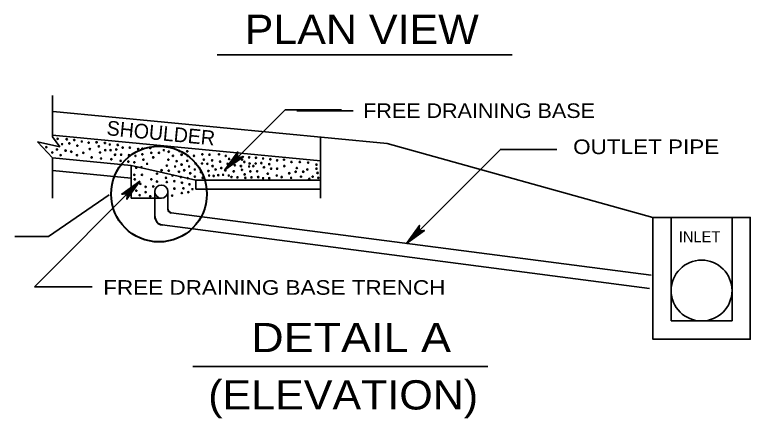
# Model space of a CAD drawing. Extents: x -48732 to -48696.6, y -117659.8 to -117637.8.
# Drawn here: x -48725.29 to -48719.25, y -117648.12 to -117644.8 of the extents above; entities that cross this region are included whole.
import ezdxf

# ---------------------------------------------------------------- set-up
doc = ezdxf.new("R2010")
doc.units = 0
doc.header["$LTSCALE"] = 0.048
doc.layers.add('1', color=7, linetype='Continuous', lineweight=25)
doc.layers.add('3', color=7, linetype='Continuous', lineweight=35)

msp = doc.modelspace()

# ---------------------------------------------------------------- linework, layer by layer
at = {"layer": '1', "lineweight": 40}
msp.add_circle((-48724.10882, -117646.27628), 0.39328, dxfattribs=at)
for centre, radius, end in [((-48724.00558, -117646.39991), 0.03, 262.57441), ((-48724.07358, -117646.45961), 0.07, 262.57442), ((-48724.07358, -117646.45961), 0.07, 262.57442)]:
    msp.add_arc(centre, radius, 180, end, dxfattribs=at)
at = {"layer": '3'}
for p, q in [((-48723.6305, -117645.13408), (-48721.20992, -117645.13408)), ((-48724.98458, -117645.46833), (-48724.98458, -117645.80533)), ((-48724.97758, -117645.59733), (-48722.23658, -117645.86133)), ((-48723.5735, -117646.08625), (-48723.0735, -117645.58625)), ((-48723.0735, -117645.58625), (-48722.6105, -117645.58625)), ((-48722.97633, -117645.5935), (-48722.51333, -117645.5935)), ((-48724.98458, -117645.79233), (-48722.78258, -117646.00433)), ((-48725.10558, -117645.84733), (-48724.98458, -117645.97933)), ((-48725.10558, -117645.84733), (-48724.92258, -117645.88733)), ((-48724.98458, -117645.80533), (-48724.92258, -117645.88733)), ((-48722.78258, -117645.80833), (-48722.78258, -117646.31033)), ((-48720.05358, -117646.46833), (-48722.23658, -117645.86133)), ((-48724.98458, -117645.97933), (-48724.98458, -117646.31033)), ((-48724.98458, -117646.08333), (-48724.33858, -117646.14533)), ((-48724.33858, -117646.04133), (-48723.80758, -117646.16333)), ((-48725.13233, -117647.03708), (-48724.26633, -117646.17108)), ((-48723.80758, -117646.16333), (-48722.78258, -117646.16333)), ((-48723.80758, -117646.23533), (-48723.80758, -117646.16333)), ((-48724.14358, -117646.25633), (-48724.14358, -117646.45958)), ((-48724.03558, -117646.25633), (-48724.03558, -117646.39992)), ((-48723.80758, -117646.23533), (-48722.78258, -117646.23533)), ((-48725.01625, -117646.62567), (-48724.51717, -117646.28358)), ((-48724.33858, -117646.31033), (-48724.08958, -117646.31033)), ((-48724.0095, -117646.42967), (-48720.0675, -117646.94342)), ((-48719.90358, -117647.31833), (-48719.90358, -117646.46833)), ((-48719.40358, -117646.46833), (-48719.40358, -117647.31833)), ((-48724.08267, -117646.529), (-48720.0815, -117647.0505)), ((-48725.29367, -117646.62567), (-48725.01625, -117646.62567)), ((-48725.13233, -117647.03708), (-48724.65858, -117647.03708)), ((-48719.40358, -117647.31833), (-48719.90358, -117647.31833)), ((-48723.83025, -117647.69208), (-48721.40967, -117647.69208))]:
    msp.add_line(p, q, dxfattribs=at)
for points in [[(-48722.07683, -117646.6815), (-48721.305, -117645.90967), (-48720.842, -117645.90967)], [(-48723.462, -117645.93042), (-48723.568, -117646.07842), (-48723.42, -117645.97242), (-48723.425, -117645.97242), (-48723.555, -117646.06542), (-48723.462, -117645.93542), (-48723.463, -117645.94142), (-48723.542, -117646.05242), (-48723.431, -117645.97342), (-48723.437, -117645.97442), (-48723.529, -117646.03942), (-48723.464, -117645.94742), (-48723.464, -117645.95342), (-48723.516, -117646.02642), (-48723.443, -117645.97442), (-48723.449, -117645.97542), (-48723.504, -117646.01442), (-48723.465, -117645.95942), (-48723.465, -117645.96542), (-48723.491, -117646.00142), (-48723.455, -117645.97542), (-48723.461, -117645.97642), (-48723.478, -117645.98842), (-48723.466, -117645.97142), (-48723.462, -117645.93042), (-48723.466, -117645.97642), (-48723.42, -117645.97242)], [(-48724.98458, -117645.97933), (-48724.33858, -117646.04133), (-48724.33858, -117646.31033)], [(-48724.37233, -117646.31908), (-48724.26633, -117646.17108), (-48724.41433, -117646.27708), (-48724.40933, -117646.27708), (-48724.27933, -117646.18408), (-48724.37233, -117646.31408), (-48724.37133, -117646.30808), (-48724.29233, -117646.19708), (-48724.40333, -117646.27608), (-48724.39733, -117646.27508), (-48724.30533, -117646.21008), (-48724.37033, -117646.30208), (-48724.37033, -117646.29608), (-48724.31833, -117646.22308), (-48724.39133, -117646.27508), (-48724.38533, -117646.27408), (-48724.33033, -117646.23508), (-48724.36933, -117646.29008), (-48724.36933, -117646.28408), (-48724.34333, -117646.24808), (-48724.37933, -117646.27408), (-48724.37333, -117646.27308), (-48724.35633, -117646.26108), (-48724.36833, -117646.27808), (-48724.37233, -117646.31908), (-48724.36833, -117646.27308), (-48724.41433, -117646.27708)], [(-48721.97083, -117646.5335), (-48722.07683, -117646.6815), (-48721.92883, -117646.5755), (-48721.93383, -117646.5755), (-48722.06383, -117646.6685), (-48721.97083, -117646.5385), (-48721.97183, -117646.5445), (-48722.05083, -117646.6555), (-48721.93983, -117646.5765), (-48721.94583, -117646.5775), (-48722.03783, -117646.6425), (-48721.97283, -117646.5505), (-48721.97283, -117646.5565), (-48722.02483, -117646.6295), (-48721.95183, -117646.5775), (-48721.95783, -117646.5785), (-48722.01283, -117646.6175), (-48721.97383, -117646.5625), (-48721.97383, -117646.5685), (-48721.99983, -117646.6045), (-48721.96383, -117646.5785), (-48721.96983, -117646.5795), (-48721.98683, -117646.5915), (-48721.97483, -117646.5745), (-48721.97083, -117646.5335), (-48721.97483, -117646.5795), (-48721.92883, -117646.5755)]]:
    msp.add_lwpolyline(points, dxfattribs=at)
msp.add_lwpolyline([(-48720.05358, -117646.46833), (-48719.25358, -117646.46833), (-48719.25358, -117647.46833), (-48720.05358, -117647.46833)], close=True, dxfattribs=at)
for centre, radius in [((-48724.94092, -117645.82333), 0.00515), ((-48724.8665, -117645.82642), 0.00515), ((-48724.80442, -117645.83267), 0.00515), ((-48724.74242, -117645.84508), 0.00515), ((-48724.68658, -117645.85442), 0.00515), ((-48724.62142, -117645.85125), 0.00515), ((-48724.55317, -117645.8575), 0.00515), ((-48725.034, -117645.89158), 0.00515), ((-48724.94717, -117645.91025), 0.00515), ((-48724.90375, -117645.86683), 0.00515), ((-48724.84542, -117645.86042), 0.00515), ((-48724.77958, -117645.87917), 0.00515), ((-48724.67725, -117645.90717), 0.00515), ((-48724.60275, -117645.88542), 0.00515), ((-48724.55008, -117645.91642), 0.00515), ((-48724.51283, -117645.86992), 0.00515), ((-48724.50658, -117645.91642), 0.00515), ((-48724.46008, -117645.91025), 0.00515), ((-48724.44767, -117645.873), 0.00515), ((-48724.40733, -117645.89475), 0.00515), ((-48724.34842, -117645.89475), 0.00515), ((-48724.28017, -117645.90717), 0.00515), ((-48724.246, -117645.904), 0.00515), ((-48724.18092, -117645.89783), 0.00515), ((-48724.06917, -117645.91642), 0.00515), ((-48724.98433, -117645.93508), 0.00515), ((-48724.91608, -117645.95683), 0.00515), ((-48724.87575, -117645.91958), 0.00515), ((-48724.82925, -117645.92883), 0.00515), ((-48724.78275, -117645.95683), 0.00515), ((-48724.73, -117645.93817), 0.00515), ((-48724.66175, -117645.97542), 0.00515), ((-48724.5935, -117645.93508), 0.00515), ((-48724.46942, -117645.95367), 0.00515), ((-48724.41975, -117645.95367), 0.00515), ((-48724.35458, -117645.95683), 0.00515), ((-48724.30183, -117645.963), 0.00515), ((-48724.246, -117645.95058), 0.00515), ((-48724.17158, -117645.93817), 0.00515), ((-48724.15608, -117645.97542), 0.00515), ((-48724.1095, -117645.93817), 0.00515), ((-48724.02883, -117645.92883), 0.00515), ((-48723.99475, -117645.963), 0.00515), ((-48723.942, -117645.92267), 0.00515), ((-48723.92342, -117645.95367), 0.00515), ((-48723.87683, -117645.92575), 0.00515), ((-48723.87375, -117645.963), 0.00515), ((-48723.821, -117645.963), 0.00515), ((-48723.75275, -117645.95058), 0.00515), ((-48723.69383, -117645.95367), 0.00515), ((-48723.61625, -117645.95058), 0.00515), ((-48723.56042, -117645.963), 0.00515), ((-48723.47667, -117645.95992), 0.00515), ((-48723.42083, -117645.97233), 0.00515), ((-48723.36808, -117645.97542), 0.00515), ((-48723.31225, -117645.9785), 0.00515), ((-48724.58417, -117645.98475), 0.00515), ((-48724.50042, -117645.99092), 0.00515), ((-48724.42283, -117646.00333), 0.00515), ((-48724.36083, -117646.00958), 0.00515), ((-48724.31117, -117646.01575), 0.00515), ((-48724.23675, -117645.99408), 0.00515), ((-48724.20567, -117646.02817), 0.00515), ((-48724.032, -117645.99408), 0.00515), ((-48723.96375, -117646.00642), 0.00515), ((-48723.92342, -117646.03442), 0.00515), ((-48723.87683, -117646.00333), 0.00515), ((-48723.80858, -117646.02508), 0.00515), ((-48723.75592, -117646.02508), 0.00515), ((-48723.74033, -117645.99408), 0.00515), ((-48723.71242, -117646.02817), 0.00515), ((-48723.67208, -117646.00025), 0.00515), ((-48723.607, -117646.00958), 0.00515), ((-48723.54492, -117646.02817), 0.00515), ((-48723.5325, -117645.98783), 0.00515), ((-48723.48292, -117645.99092), 0.00515), ((-48723.427, -117645.99408), 0.00515), ((-48723.40842, -117646.01267), 0.00515), ((-48723.365, -117646.02508), 0.00515), ((-48723.31533, -117646.02508), 0.00515), ((-48723.26883, -117646.022), 0.00515), ((-48723.25333, -117645.98475), 0.00515), ((-48723.20367, -117646.03125), 0.00515), ((-48723.19433, -117645.99092), 0.00515), ((-48723.1385, -117646.00025), 0.00515), ((-48723.08267, -117645.99408), 0.00515), ((-48723.02067, -117646.01267), 0.00515), ((-48722.95242, -117646.01267), 0.00515), ((-48722.88417, -117646.01883), 0.00515), ((-48722.81592, -117646.03442), 0.00515), ((-48724.29567, -117646.05925), 0.00515), ((-48724.25225, -117646.05608), 0.00515), ((-48724.08783, -117646.08092), 0.00515), ((-48724.04442, -117646.04367), 0.00515), ((-48724.02883, -117646.08408), 0.00515), ((-48723.97617, -117646.04992), 0.00515), ((-48723.94508, -117646.09333), 0.00515), ((-48723.90167, -117646.08092), 0.00515), ((-48723.86133, -117646.04992), 0.00515), ((-48723.81483, -117646.07475), 0.00515), ((-48723.76517, -117646.0965), 0.00515), ((-48723.70317, -117646.08717), 0.00515), ((-48723.669, -117646.04683), 0.00515), ((-48723.64417, -117646.07475), 0.00515), ((-48723.59767, -117646.06233), 0.00515), ((-48723.5635, -117646.08092), 0.00515), ((-48723.49525, -117646.09025), 0.00515), ((-48723.486, -117646.04058), 0.00515), ((-48723.43633, -117646.04683), 0.00515), ((-48723.427, -117646.07783), 0.00515), ((-48723.36808, -117646.04992), 0.00515), ((-48723.35875, -117646.09025), 0.00515), ((-48723.334, -117646.04683), 0.00515), ((-48723.30292, -117646.09025), 0.00515), ((-48723.24708, -117646.05608), 0.00515), ((-48723.18817, -117646.0685), 0.00515), ((-48723.1385, -117646.0685), 0.00515), ((-48723.07958, -117646.04683), 0.00515), ((-48722.9865, -117646.09333), 0.00515), ((-48722.97725, -117646.06233), 0.00515), ((-48722.9245, -117646.09333), 0.00515), ((-48722.89033, -117646.07475), 0.00515), ((-48722.81592, -117646.0685), 0.00515), ((-48724.31117, -117646.11817), 0.00515), ((-48724.30808, -117646.15542), 0.00515), ((-48724.24917, -117646.11817), 0.00515), ((-48724.17158, -117646.15542), 0.00515), ((-48724.12508, -117646.10892), 0.00515), ((-48724.05058, -117646.143), 0.00515), ((-48723.99783, -117646.12442), 0.00515), ((-48723.92958, -117646.13683), 0.00515), ((-48723.87375, -117646.14608), 0.00515), ((-48723.85208, -117646.10575), 0.00515), ((-48723.81483, -117646.13367), 0.00515), ((-48723.74967, -117646.143), 0.00515), ((-48723.69692, -117646.12442), 0.00515), ((-48723.65967, -117646.1275), 0.00515), ((-48723.6225, -117646.12133), 0.00515), ((-48723.58217, -117646.11817), 0.00515), ((-48723.53558, -117646.12442), 0.00515), ((-48723.51392, -117646.13683), 0.00515), ((-48723.46425, -117646.13992), 0.00515), ((-48723.40533, -117646.11508), 0.00515), ((-48723.39908, -117646.143), 0.00515), ((-48723.3495, -117646.13992), 0.00515), ((-48723.29367, -117646.13683), 0.00515), ((-48723.25333, -117646.14608), 0.00515), ((-48723.21608, -117646.10892), 0.00515), ((-48723.20367, -117646.14608), 0.00515), ((-48723.14167, -117646.12442), 0.00515), ((-48723.10133, -117646.13683), 0.00515), ((-48723.03925, -117646.10575), 0.00515), ((-48723.02375, -117646.143), 0.00515), ((-48722.94308, -117646.13367), 0.00515), ((-48722.87483, -117646.15233), 0.00515), ((-48722.84692, -117646.13367), 0.00515), ((-48722.80658, -117646.10267), 0.00515), ((-48722.80042, -117646.143), 0.00515), ((-48724.26158, -117646.19267), 0.00515), ((-48724.21808, -117646.2175), 0.00515), ((-48724.15608, -117646.21442), 0.00515), ((-48724.08958, -117646.25633), 0.054), ((-48724.12508, -117646.17408), 0.00515), ((-48724.04442, -117646.17717), 0.00515), ((-48723.98233, -117646.17092), 0.00515), ((-48723.92033, -117646.18333), 0.00515), ((-48723.85825, -117646.19575), 0.00515), ((-48724.29567, -117646.24858), 0.00515), ((-48724.21808, -117646.261), 0.00515), ((-48723.98231, -117646.23157), 0.00515), ((-48723.92173, -117646.26748), 0.00515), ((-48723.90823, -117646.22932), 0.00515), ((-48723.8679, -117646.26073), 0.00515), ((-48723.83423, -117646.23607), 0.00515), ((-48724.26775, -117646.28575), 0.00515), ((-48724.18092, -117646.29508), 0.00515), ((-48724.00031, -117646.2899), 0.00515), ((-48719.65358, -117647.06833), 0.25)]:
    msp.add_circle(centre, radius, dxfattribs=at)

# ---------------------------------------------------------------- texts
for s, height, width, p in [('PLAN VIEW', 0.24, 1.1, (-48723.40558, -117645.04417)), ('FREE DRAINING BASE', 0.12, 1.1, (-48722.43192, -117645.65192)), ('OUTLET PIPE', 0.12, 1.15, (-48720.70833, -117645.94833)), ('FREE DRAINING BASE TRENCH', 0.12, 1.15, (-48724.56658, -117647.10317)), ('DETAIL A', 0.24, 1.15, (-48723.35158, -117647.574)), ('(ELEVATION)', 0.24, 1.1, (-48723.70483, -117648.04475))]:
    msp.add_text(s, height=height, dxfattribs=dict(at, width=width)).set_placement(p)
msp.add_text('SHOULDER', height=0.12, rotation=354.497, dxfattribs=at).set_placement((-48724.54258, -117645.79233))
msp.add_text('INLET', height=0.09, dxfattribs=at).set_placement((-48719.84058, -117646.67133))

doc.saveas('drawing.dxf')
